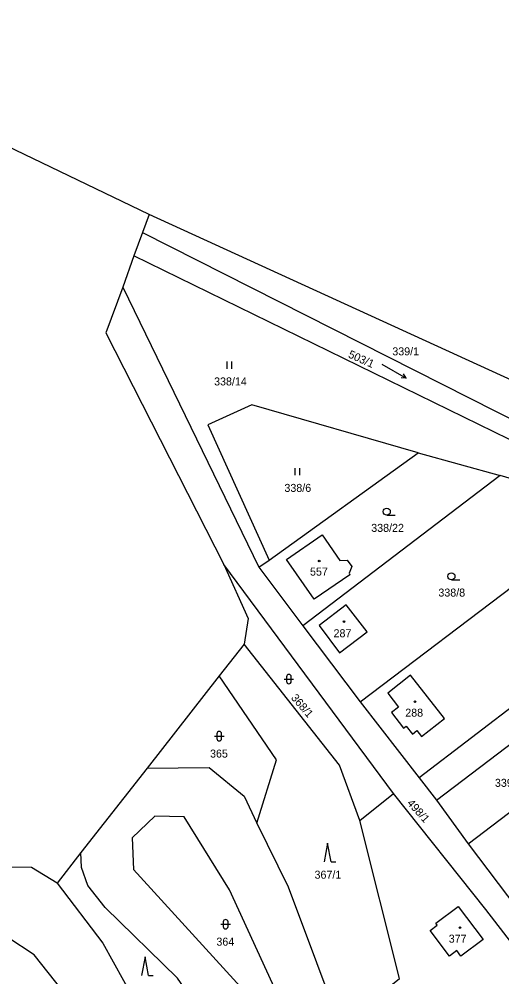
# Model space of a CAD drawing. Extents: x -725728 to -720881, y -1068679 to -1063504.
# Drawn here: x -723846.7 to -723744.1, y -1066824.1 to -1066620.7 of the extents above; entities that cross this region are included whole.
import ezdxf

# ---------------------------------------------------------------- set-up
doc = ezdxf.new("R2010")
doc.units = 0
for name, color, linetype in [('Hranice parcel', 7, 'Continuous'), ('Parcelní čísla', 7, 'Continuous'), ('Značky budov', 7, 'Continuous'), ('Značky kultur', 7, 'Continuous')]:
    doc.layers.add(name, color=color, linetype=linetype)

# ---------------------------------------------------------------- blocks, each defined once
blk = doc.blocks.new('4.02_3')
at = {"layer": 'Značky budov'}
blk.add_circle((-0.001, 0), 0.0175, dxfattribs=at)
blk = doc.blocks.new('3.06_1')
at = {"layer": 'Značky kultur'}
for p, q in [((-0.051, 0), (-0.051, 0.15)), ((0.049, 0), (0.049, 0.15))]:
    blk.add_line(p, q, dxfattribs=at)
blk = doc.blocks.new('3.04_2')
at = {"layer": 'Značky kultur'}
blk.add_line((0.001, 0), (0.176, 0), dxfattribs=at)
blk.add_circle((0.001, 0.075), 0.075, dxfattribs=at)
blk = doc.blocks.new('3.08_1')
at = {"layer": 'Značky kultur'}
for p, q in [((0, 0.4), (-0.075, 0)), ((0.075, 0), (0, 0.4)), ((0.075, 0), (0.175, 0))]:
    blk.add_line(p, q, dxfattribs=at)
blk = doc.blocks.new('3.16_3')
at = {"layer": 'Značky kultur'}
for p, q in [((-0.1, 0.1), (0.1, 0.1)), ((-0.05, 0.15), (-0.05, 0.05)), ((0.05, 0.05), (0.05, 0.15))]:
    blk.add_line(p, q, dxfattribs=at)
for centre, start, end in [((0, 0.15), 0, 180), ((0, 0.05), 180, 359.9879)]:
    blk.add_arc(centre, 0.05, start, end, dxfattribs=at)
blk = doc.blocks.new('3.16_2')
at = {"layer": 'Značky kultur'}
for p, q in [((-0.1, 0.1), (0.1, 0.1)), ((-0.05, 0.15), (-0.05, 0.05)), ((0.05, 0.05), (0.05, 0.15))]:
    blk.add_line(p, q, dxfattribs=at)
for centre, start, end in [((0, 0.15), 0, 180), ((0, 0.05), 180, 359.9879)]:
    blk.add_arc(centre, 0.05, start, end, dxfattribs=at)
blk = doc.blocks.new('3.08_2')
at = {"layer": 'Značky kultur'}
for p, q in [((0, 0.4), (-0.075, 0)), ((0.075, 0), (0, 0.4)), ((0.075, 0), (0.175, 0))]:
    blk.add_line(p, q, dxfattribs=at)
blk = doc.blocks.new('3.06_2')
at = {"layer": 'Značky kultur'}
for p, q in [((-0.051, 0), (-0.051, 0.15)), ((0.049, 0), (0.049, 0.15))]:
    blk.add_line(p, q, dxfattribs=at)
blk = doc.blocks.new('8.02_27')
at = {"layer": 'Značky kultur'}
for p, q in [((-0.259, 0.148), (0.261, -0.152)), ((0.261, -0.152), (0.151, -0.146)), ((0.261, -0.152), (0.201, -0.059))]:
    blk.add_line(p, q, dxfattribs=at)

msp = doc.modelspace()

# ---------------------------------------------------------------- linework, layer by layer
at = {"layer": 'Hranice parcel'}
for p, q in [((-723819.02, -1066662.15), (-723907.93, -1066619.51)), ((-723819.02, -1066662.15), (-723820.41, -1066665.95)), ((-723722.66, -1066706.21), (-723819.02, -1066662.15)), ((-723820.41, -1066665.95), (-723822.27, -1066670.94)), ((-723820.41, -1066665.95), (-723709.16, -1066722.32)), ((-723822.27, -1066670.94), (-723824.59, -1066677.56)), ((-723714.54, -1066723.57), (-723822.27, -1066670.94)), ((-723824.59, -1066677.56), (-723795.7, -1066737.08)), ((-723793.54, -1066735.53), (-723761.85, -1066712.76)), ((-723761.85, -1066712.76), (-723744.41, -1066717.6)), ((-723744.41, -1066717.6), (-723786.36, -1066749.49)), ((-723720.19, -1066724.74), (-723744.41, -1066717.6)), ((-723774.21, -1066765.63), (-723720.19, -1066724.74)), ((-723767.08, -1066785.15), (-723803.15, -1066736.48)), ((-723795.7, -1066737.08), (-723793.54, -1066735.53)), ((-723795.7, -1066737.08), (-723786.36, -1066749.49)), ((-723713.15, -1066744.75), (-723761.67, -1066781.77)), ((-723786.36, -1066749.49), (-723774.21, -1066765.63)), ((-723798.85, -1066753.4), (-723804.12, -1066760.13)), ((-723804.12, -1066760.13), (-723819.47, -1066779.73)), ((-723774.21, -1066765.63), (-723761.67, -1066781.77)), ((-723757.94, -1066786.56), (-723737.17, -1066770.73)), ((-723819.47, -1066779.73), (-723833.53, -1066797.67)), ((-723751.25, -1066795.83), (-723730.11, -1066779.73)), ((-723761.67, -1066781.77), (-723757.94, -1066786.56)), ((-723774.26, -1066790.88), (-723767.08, -1066785.15)), ((-723757.94, -1066786.56), (-723751.25, -1066795.83)), ((-723833.53, -1066797.67), (-723838.61, -1066804.15)), ((-723751.25, -1066795.83), (-723740.67, -1066809.73))]:
    msp.add_line(p, q, dxfattribs=at)
for points in [[(-723824.59, -1066677.56), (-723828.22, -1066687.31), (-723803.15, -1066736.48)], [(-723761.85, -1066712.76), (-723797.19, -1066702.6), (-723806.57, -1066706.85), (-723793.54, -1066735.53)], [(-723789.87, -1066735.41), (-723782.27, -1066730.21), (-723778.47, -1066735.63), (-723776.92, -1066735.53), (-723775.94, -1066736.91), (-723776.55, -1066738.33), (-723776.36, -1066738.64), (-723783.98, -1066743.85), (-723789.87, -1066735.41)], [(-723803.15, -1066736.48), (-723797.97, -1066747.97), (-723798.85, -1066753.4)], [(-723777.15, -1066745.04), (-723782.93, -1066749.43), (-723778.54, -1066755.21), (-723772.72, -1066750.79), (-723777.15, -1066745.04)], [(-723774.26, -1066790.88), (-723778.54, -1066779.07), (-723798.85, -1066753.4)], [(-723796.13, -1066791.39), (-723791.94, -1066777.99), (-723804.12, -1066760.13)], [(-723763.5, -1066760.01), (-723768.32, -1066763.79), (-723766, -1066766.77), (-723767.49, -1066767.93), (-723764.99, -1066771.22), (-723764.43, -1066770.78), (-723763.08, -1066772.51), (-723762.11, -1066771.76), (-723761.14, -1066773.01), (-723756.29, -1066769.2), (-723763.5, -1066760.01)], [(-723819.47, -1066779.73), (-723806.29, -1066779.61), (-723798.84, -1066785.71), (-723796.13, -1066791.39)], [(-723736.18, -1066824.32), (-723737.88, -1066822.12), (-723747.44, -1066809.73), (-723767.08, -1066785.15)], [(-723822.39, -1066801.28), (-723792.35, -1066834.18), (-723782.47, -1066857.47), (-723772.78, -1066874.14), (-723790.04, -1066831.48), (-723801.95, -1066805.61), (-723811.56, -1066790.04), (-723817.79, -1066789.91), (-723822.66, -1066794.51), (-723822.39, -1066801.28)], [(-723796.13, -1066791.39), (-723789.5, -1066804.93), (-723777.46, -1066837.1)], [(-723772.18, -1066840.99), (-723775.66, -1066832.33), (-723765.79, -1066824.42), (-723774.26, -1066790.88)], [(-723803.27, -1066838.36), (-723812.99, -1066824.35), (-723828.38, -1066809.32), (-723832.04, -1066804.65), (-723833.43, -1066800.86), (-723833.53, -1066797.67)], [(-723838.61, -1066804.15), (-723844.03, -1066800.86), (-723851.48, -1066800.74), (-723859.05, -1066803.89)], [(-723838.61, -1066804.15), (-723828.89, -1066816.9), (-723813.49, -1066844.67)], [(-723748.07, -1066816.09), (-723752.77, -1066819.64), (-723753.66, -1066818.47), (-723755.22, -1066819.66), (-723759.29, -1066814.18), (-723757.81, -1066813.05), (-723758.11, -1066812.66), (-723753.37, -1066809.08), (-723748.07, -1066816.09)], [(-723821.23, -1066849.15), (-723828.32, -1066838.46), (-723843.47, -1066819.39), (-723849.08, -1066815.73), (-723853.94, -1066822.36), (-723852.74, -1066828.17), (-723845.99, -1066846.28), (-723844.74, -1066876.41)]]:
    msp.add_lwpolyline(points, dxfattribs=at)

# ---------------------------------------------------------------- block references
at = {"layer": 'Značky budov', "xscale": 10, "yscale": 10}
for p in [(-723782.87, -1066735.75), (-723777.62, -1066748.59), (-723762.53, -1066765.62), (-723752.94, -1066813.61)]:
    msp.add_blockref('4.02_3', p, dxfattribs=at)
at = {"layer": 'Značky kultur', "xscale": 10, "yscale": 10}
for name, p in [('3.06_2', (-723801.93, -1066694.9)), ('8.02_27', (-723767, -1066695.4)), ('3.06_1', (-723787.51, -1066717.51)), ('3.04_2', (-723768.53, -1066726)), ('3.04_2', (-723754.79, -1066739.74)), ('3.16_2', (-723789.34, -1066761.81)), ('3.16_2', (-723804.12, -1066773.94)), ('3.08_2', (-723781.11, -1066799.66)), ('3.16_3', (-723802.77, -1066813.88)), ('3.08_1', (-723819.9, -1066823.79))]:
    msp.add_blockref(name, p, dxfattribs=at)

# ---------------------------------------------------------------- texts
at = {"layer": 'Parcelní čísla'}
for s, rotation, p in [('503/1', 336, (-723776.86, -1066692.45)), ('368/1', 311, (-723788.99, -1066764.87)), ('498/1', 312, (-723764.33, -1066787.26))]:
    msp.add_text(s, height=1.7, rotation=rotation, dxfattribs=at).set_placement(p)
for s, p in [('339/1', (-723767.35, -1066692.06)), ('338/14', (-723805.23, -1066698.45)), ('338/6', (-723790.28, -1066721.06)), ('338/22', (-723771.83, -1066729.55)), ('557', (-723784.84, -1066738.84)), ('338/8', (-723757.56, -1066743.29)), ('287', (-723779.84, -1066751.93)), ('288', (-723764.6, -1066768.8)), ('365', (-723806.09, -1066777.49)), ('339/8', (-723745.54, -1066783.7)), ('367/1', (-723783.88, -1066803.21)), ('364', (-723804.74, -1066817.43)), ('377', (-723755.36, -1066816.79))]:
    msp.add_text(s, height=1.7, dxfattribs=at).set_placement(p)

doc.saveas('drawing.dxf')
